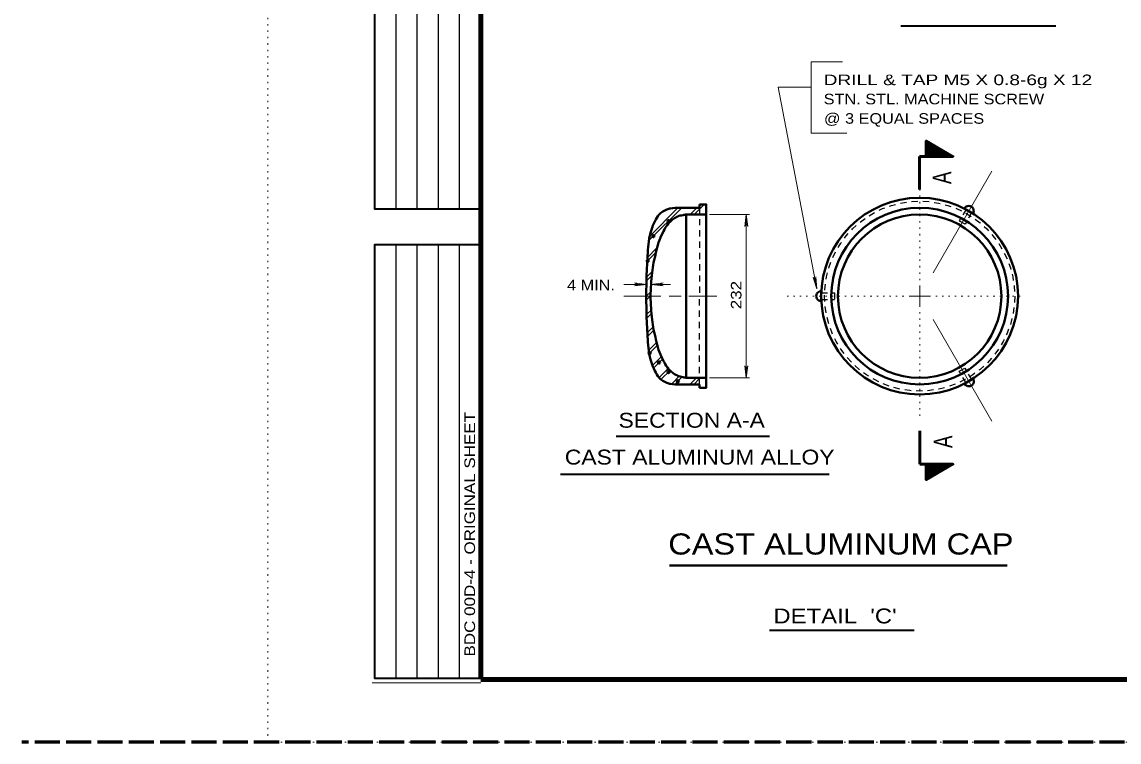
# Model space of a CAD drawing. Extents: x 312583 to 312854, y 144419 to 144597.
# Drawn here: x 312583.5 to 312662.4, y 144418.6 to 144470.4 of the extents above; entities that cross this region are included whole.
import ezdxf
from ezdxf.enums import TextEntityAlignment as Align

# ---------------------------------------------------------------- set-up
doc = ezdxf.new("R2010")
doc.units = 0
doc.header["$LTSCALE"] = 0.3
doc.header["$PDMODE"] = 32
doc.header["$PDSIZE"] = 0.15
for name, pattern in [('DOTTED', [1.5, 0.3, -1.2]), ('LONG_DASHED', [7.5, 6, -1.5]), ('SHORT_DASHED', [2.7, 1.5, -1.2])]:
    doc.linetypes.add(name, pattern=pattern)
for name, color, linetype, lineweight in [('1', 7, 'Continuous', 40), ('2', 7, 'Continuous', 13), ('62', 7, 'DOTTED', 13), ('63', 7, 'LONG_DASHED', 60)]:
    doc.layers.add(name, color=color, linetype=linetype, lineweight=lineweight)

msp = doc.modelspace()

# ---------------------------------------------------------------- linework, layer by layer
at = {"layer": '1', "lineweight": 25}
for p, q in [((312610.4087, 144456.901), (312610.4087, 144488.1192)), ((312611.9315, 144456.901), (312611.9315, 144488.1192)), ((312613.4543, 144456.901), (312613.4543, 144488.1192)), ((312614.9772, 144456.901), (312614.9772, 144488.1192)), ((312610.4087, 144423.1446), (312610.4087, 144454.3629)), ((312611.9315, 144423.1446), (312611.9315, 144454.3629)), ((312613.4543, 144423.1446), (312613.4543, 144454.3629)), ((312614.9772, 144423.1446), (312614.9772, 144454.3629))]:
    msp.add_line(p, q, dxfattribs=at)
at = {"layer": '1', "lineweight": 13}
for p, q in [((312653.2173, 144459.6302), (312649.0006, 144452.3239)), ((312628.6303, 144454.6852), (312630.9456, 144457.0006)), ((312628.6686, 144454.9919), (312630.6313, 144456.9622)), ((312631.5436, 144456.5176), (312632.0266, 144457.0006)), ((312631.8196, 144456.5176), (312632.5403, 144457.2382)), ((312632.2183, 144457.1922), (312632.2643, 144457.2382)), ((312628.4539, 144453.1596), (312629.0826, 144453.7806)), ((312628.4693, 144453.4356), (312629.1516, 144454.1256)), ((312628.4233, 144452.0402), (312628.8066, 144452.4236)), ((312628.4233, 144451.7642), (312628.7683, 144452.1092)), ((312628.3849, 144450.6526), (312628.7069, 144450.9669)), ((312628.3926, 144450.3842), (312628.6916, 144450.6756)), ((312628.4156, 144449.3186), (312628.7529, 144449.6559)), ((312628.4156, 144449.0502), (312628.7683, 144449.4029)), ((312653.2173, 144441.6596), (312649.0006, 144448.9659)), ((312628.4386, 144447.9846), (312628.9139, 144448.4599)), ((312628.4539, 144447.7316), (312628.9446, 144448.2299)), ((312628.5613, 144446.7579), (312629.0979, 144447.2946)), ((312628.5919, 144446.5126), (312629.1669, 144447.0952)), ((312628.8756, 144445.7152), (312629.4736, 144446.3132)), ((312628.9676, 144445.5389), (312629.5503, 144446.1139)), ((312629.3279, 144444.8106), (312629.9796, 144445.4622)), ((312629.4429, 144444.6572), (312630.1253, 144445.3319)), ((312630.2173, 144444.3506), (312630.7846, 144444.9179)), ((312630.4779, 144444.3352), (312630.9993, 144444.8566)), ((312631.5359, 144444.3122), (312632.0036, 144444.7799)), ((312631.8043, 144444.3046), (312632.2719, 144444.7799)), ((312632.6399, 144444.0592), (312632.7013, 144444.1129)), ((312608.6858, 144422.8446), (312616.5, 144422.8446))]:
    msp.add_line(p, q, dxfattribs=at)
at = {"layer": '1'}
for p, q in [((312632.2183, 144457.0006), (312630.7846, 144457.0006)), ((312632.2183, 144457.0006), (312632.2183, 144457.2382)), ((312651.2546, 144456.9469), (312651.8756, 144456.5942)), ((312631.2599, 144456.5176), (312631.2599, 144450.6449)), ((312632.7013, 144456.5176), (312632.7013, 144450.6449)), ((312631.2599, 144444.7799), (312631.2599, 144450.6449)), ((312632.7013, 144444.7799), (312632.7013, 144450.6449)), ((312640.9659, 144450.2922), (312640.9659, 144451.0052)), ((312632.2183, 144444.2969), (312630.7846, 144444.2969)), ((312632.2183, 144444.2969), (312632.2183, 144444.0592)), ((312651.8756, 144444.7032), (312651.2546, 144444.3506))]:
    msp.add_line(p, q, dxfattribs=at)
at = {"layer": '1', "linetype": 'SHORT_DASHED', "lineweight": 25}
for p, q in [((312632.2183, 144457.0006), (312632.2183, 144450.6449)), ((312651.3619, 144456.8856), (312650.8789, 144456.0576)), ((312651.2929, 144455.8199), (312650.8789, 144456.0576)), ((312651.7683, 144456.6479), (312651.2929, 144455.8199)), ((312632.2183, 144444.2969), (312632.2183, 144450.6449)), ((312640.9659, 144450.8826), (312641.9243, 144450.8826)), ((312641.9243, 144450.8826), (312641.9243, 144450.4072)), ((312640.9659, 144450.4072), (312641.9243, 144450.4072)), ((312650.8789, 144445.2399), (312651.2929, 144445.4776)), ((312651.3619, 144444.4042), (312650.8789, 144445.2399)), ((312651.7759, 144444.6496), (312651.2929, 144445.4776))]:
    msp.add_line(p, q, dxfattribs=at)
at = {"layer": '1', "lineweight": 158}
msp.add_line((312616.5, 144423.0846), (312849, 144423.0846), dxfattribs=at)
msp.add_lwpolyline([(312616.5, 144423.1446), (312616.5, 144585.0846), (312849, 144585.0846)], dxfattribs=at)
at = {"layer": '1', "lineweight": 35}
for points in [[(312616.5, 144456.901), (312608.8858, 144456.901), (312608.8858, 144488.1192), (312616.5, 144488.1192)], [(312616.5, 144423.1446), (312608.8858, 144423.1446), (312608.8858, 144454.3629), (312616.5, 144454.3629)]]:
    msp.add_lwpolyline(points, dxfattribs=at)
at = {"layer": '1'}
for points in [[(312631.2599, 144456.5176), (312632.7013, 144456.5176), (312632.7013, 144457.2382), (312632.2183, 144457.2382)], [(312631.2599, 144444.7799), (312632.7013, 144444.7799), (312632.7013, 144444.0592), (312632.2183, 144444.0592)]]:
    msp.add_lwpolyline(points, dxfattribs=at)
for radius in [7.0687, 6.3499, 5.8708]:
    msp.add_circle((312648.0308, 144450.6468), radius, dxfattribs=at)
at = {"layer": '1', "linetype": 'SHORT_DASHED', "lineweight": 25}
msp.add_circle((312648.0308, 144450.6468), 6.8291, dxfattribs=at)
at = {"layer": '1'}
for centre, start, end in [((312651.5658, 144456.7715), 329.52448, 150.47552), ((312640.9591, 144450.6459), 89.52448, 270.47552), ((312651.5674, 144444.5231), 209.52448, 30.47552)]:
    msp.add_arc(centre, 0.3575, start, end, dxfattribs=at)
for points in [[(312628.3849, 144450.6449), (312628.4079, 144452.0096), (312628.4923, 144453.7652), (312628.5689, 144454.5779), (312628.7529, 144455.4136), (312628.9983, 144456.0116), (312629.3126, 144456.5099), (312629.8723, 144456.8779), (312630.1329, 144456.9546), (312630.7846, 144457.0006)], [(312631.2599, 144456.5176), (312631.0299, 144456.4716), (312630.8153, 144456.4332), (312630.5009, 144456.3029), (312630.2019, 144456.0959), (312629.8186, 144455.6589), (312629.5733, 144455.1989), (312629.2743, 144454.5012), (312629.0826, 144453.7729), (312628.9139, 144453.0599), (312628.8066, 144452.3392), (312628.6839, 144450.6296)], [(312628.3849, 144450.6449), (312628.4079, 144449.2879), (312628.4923, 144447.5322), (312628.5689, 144446.7119), (312628.7529, 144445.8839), (312628.9983, 144445.2859), (312629.3126, 144444.7799), (312629.8723, 144444.4119), (312630.1329, 144444.3352), (312630.7846, 144444.2969)], [(312631.2599, 144444.7799), (312631.0299, 144444.8182), (312630.8153, 144444.8642), (312630.5009, 144444.9946), (312630.2019, 144445.2016), (312629.8186, 144445.6386), (312629.5733, 144446.0986), (312629.2743, 144446.7962), (312629.0826, 144447.5246), (312628.9139, 144448.2376), (312628.8066, 144448.9506), (312628.6839, 144450.6296)]]:
    msp.add_spline(points, degree=3, dxfattribs=at)
for p in [(312629.9873, 144456.0422), (312628.8986, 144454.9536), (312628.4923, 144453.1902), (312628.6303, 144446.5509), (312629.3049, 144445.8762), (312629.9873, 144445.1939), (312630.6619, 144444.5192)]:
    msp.add_point(p, dxfattribs=at)
at = {"layer": '2', "lineweight": 35}
for p, q in [((312646.6866, 144470.0876), (312657.8216, 144470.0876)), ((312648.5023, 144461.7769), (312648.5176, 144461.7922)), ((312648.5023, 144461.7309), (312648.5406, 144461.7846)), ((312648.5023, 144461.6772), (312648.5559, 144461.7692)), ((312648.5023, 144461.6312), (312648.5789, 144461.7539)), ((312648.5023, 144461.5776), (312648.6019, 144461.7462)), ((312648.5023, 144461.5392), (312648.6173, 144461.7309)), ((312648.5023, 144461.4856), (312648.6403, 144461.7232)), ((312648.5023, 144461.4396), (312648.6633, 144461.7079)), ((312648.5023, 144461.3936), (312648.6786, 144461.7002)), ((312648.5023, 144461.3476), (312648.7093, 144461.6849)), ((312648.5023, 144461.2939), (312648.7246, 144461.6772)), ((312648.5023, 144461.2479), (312648.7476, 144461.6619)), ((312648.5023, 144461.2019), (312648.7706, 144461.6542)), ((312648.5023, 144461.1482), (312648.7859, 144461.6389)), ((312648.5023, 144461.1022), (312648.8089, 144461.6312)), ((312648.5023, 144461.0562), (312648.8243, 144461.6159)), ((312648.5023, 144461.0026), (312648.8473, 144461.6006)), ((312648.5023, 144460.9566), (312648.8703, 144461.5929)), ((312648.5023, 144460.9106), (312648.8856, 144461.5776)), ((312648.5023, 144460.8646), (312648.9086, 144461.5622)), ((312648.5023, 144460.8109), (312648.9316, 144461.5546)), ((312648.5023, 144460.7726), (312648.9469, 144461.5392)), ((312648.5023, 144460.7189), (312648.9776, 144461.5316)), ((312648.5176, 144460.6959), (312648.9929, 144461.5162)), ((312648.5483, 144460.6959), (312649.0159, 144461.5086)), ((312648.5789, 144460.6959), (312649.0389, 144461.4932)), ((312648.6019, 144460.6959), (312649.0543, 144461.4856)), ((312648.6326, 144460.6959), (312649.0773, 144461.4702)), ((312648.6556, 144460.7036), (312649.1003, 144461.4626)), ((312648.6863, 144460.7036), (312649.1156, 144461.4472)), ((312648.7093, 144460.6959), (312649.1386, 144461.4396)), ((312648.7399, 144460.6959), (312649.1616, 144461.4242)), ((312648.7706, 144460.6959), (312649.1769, 144461.4089)), ((312648.7936, 144460.6959), (312649.1999, 144461.4012)), ((312648.8243, 144460.6959), (312649.2229, 144461.3859)), ((312648.8549, 144460.6959), (312649.2459, 144461.3706)), ((312648.8779, 144460.6959), (312649.2613, 144461.3629)), ((312648.9086, 144460.7036), (312649.2843, 144461.3476)), ((312648.9393, 144460.6959), (312649.3073, 144461.3399)), ((312648.9623, 144460.6959), (312649.3226, 144461.3246)), ((312648.9853, 144460.6959), (312649.3456, 144461.3169)), ((312649.0159, 144460.6959), (312649.3686, 144461.3016)), ((312649.0466, 144460.6959), (312649.3839, 144461.2939)), ((312649.0773, 144460.6959), (312649.4069, 144461.2786)), ((312649.1003, 144460.6959), (312649.4299, 144461.2709)), ((312649.1309, 144460.6959), (312649.4453, 144461.2556)), ((312649.1539, 144460.7036), (312649.4759, 144461.2479)), ((312649.1846, 144460.6959), (312649.4913, 144461.2326)), ((312649.2076, 144460.6959), (312649.5143, 144461.2172)), ((312649.2383, 144460.6959), (312649.5373, 144461.2096)), ((312649.2689, 144460.6959), (312649.5526, 144461.1942)), ((312649.2919, 144460.6959), (312649.5756, 144461.1866)), ((312649.3226, 144460.6959), (312649.5986, 144461.1712)), ((312649.3533, 144460.6959), (312649.6139, 144461.1636)), ((312649.3763, 144460.6959), (312649.6369, 144461.1482)), ((312649.4069, 144460.6959), (312649.6599, 144461.1406)), ((312649.4376, 144460.6959), (312649.6753, 144461.1252)), ((312649.4606, 144460.6959), (312649.6983, 144461.1176)), ((312649.4836, 144460.6959), (312649.7213, 144461.1022)), ((312649.5143, 144460.6959), (312649.7443, 144461.0946)), ((312649.5449, 144460.6959), (312649.7596, 144461.0792)), ((312649.5756, 144460.6959), (312649.7826, 144461.0639)), ((312649.5986, 144460.6959), (312649.8056, 144461.0562)), ((312649.6293, 144460.6959), (312649.8209, 144461.0409)), ((312649.6523, 144460.6959), (312649.8439, 144461.0256)), ((312649.6829, 144460.6959), (312649.8669, 144461.0179)), ((312649.7059, 144460.6959), (312649.8823, 144461.0026)), ((312649.7366, 144460.6959), (312649.9053, 144460.9949)), ((312649.7673, 144460.6959), (312649.9283, 144460.9796)), ((312649.7903, 144460.6959), (312649.9436, 144460.9719)), ((312649.8209, 144460.6959), (312649.9743, 144460.9566)), ((312649.8439, 144460.6959), (312649.9896, 144460.9489)), ((312649.8746, 144460.6959), (312650.0126, 144460.9336)), ((312649.9053, 144460.6959), (312650.0356, 144460.9259)), ((312649.9283, 144460.6959), (312650.0509, 144460.9106)), ((312649.9589, 144460.6959), (312650.0739, 144460.9029)), ((312649.9819, 144460.6959), (312650.0969, 144460.8876)), ((312650.0126, 144460.6959), (312650.1123, 144460.8722)), ((312650.0433, 144460.6959), (312650.1353, 144460.8646)), ((312650.0739, 144460.6959), (312650.1583, 144460.8492)), ((312650.0969, 144460.6959), (312650.1736, 144460.8339)), ((312650.1276, 144460.6959), (312650.1966, 144460.8262)), ((312650.1506, 144460.6959), (312650.2196, 144460.8109)), ((312650.1736, 144460.6959), (312650.2426, 144460.8032)), ((312650.2043, 144460.6959), (312650.2579, 144460.7879)), ((312650.2349, 144460.6959), (312650.2809, 144460.7802)), ((312650.2656, 144460.6959), (312650.3039, 144460.7649)), ((312650.2886, 144460.6959), (312650.3193, 144460.7572)), ((312650.3193, 144460.6959), (312650.3423, 144460.7419)), ((312650.3423, 144460.6959), (312650.3653, 144460.7342)), ((312650.3729, 144460.6959), (312650.3806, 144460.7189)), ((312650.4036, 144460.6959), (312650.4036, 144460.7112)), ((312626.2306, 144440.5786), (312637.2323, 144440.5786)), ((312622.2255, 144437.8492), (312641.5409, 144437.8492)), ((312648.5099, 144438.5392), (312648.9853, 144437.7266)), ((312648.5099, 144438.4856), (312648.9546, 144437.7189)), ((312648.5099, 144438.4472), (312648.9393, 144437.7036)), ((312648.5099, 144438.3936), (312648.9163, 144437.6959)), ((312648.5099, 144438.3476), (312648.8933, 144437.6806)), ((312648.5099, 144438.3016), (312648.8779, 144437.6652)), ((312648.5099, 144438.2556), (312648.8549, 144437.6576)), ((312648.5099, 144438.2019), (312648.8319, 144437.6422)), ((312648.5099, 144438.1559), (312648.8166, 144437.6269)), ((312648.5099, 144438.1099), (312648.7936, 144437.6192)), ((312648.5099, 144438.0562), (312648.7783, 144437.6039)), ((312648.5099, 144438.0102), (312648.7553, 144437.5962)), ((312648.5099, 144437.9642), (312648.7323, 144437.5809)), ((312648.5099, 144437.9106), (312648.7169, 144437.5732)), ((312648.5099, 144437.8646), (312648.6863, 144437.5579)), ((312648.5253, 144438.5622), (312649.0006, 144437.7419)), ((312648.5559, 144438.5622), (312649.0236, 144437.7496)), ((312648.5866, 144438.5622), (312649.0466, 144437.7649)), ((312648.6096, 144438.5622), (312649.0619, 144437.7726)), ((312648.6403, 144438.5622), (312649.0849, 144437.7879)), ((312648.6633, 144438.5546), (312649.1079, 144437.7956)), ((312648.6939, 144438.5546), (312649.1233, 144437.8109)), ((312648.7169, 144438.5622), (312649.1463, 144437.8186)), ((312648.7476, 144438.5622), (312649.1693, 144437.8339)), ((312648.7783, 144438.5622), (312649.1846, 144437.8492)), ((312648.8013, 144438.5622), (312649.2076, 144437.8569)), ((312648.8319, 144438.5622), (312649.2306, 144437.8722)), ((312648.8626, 144438.5622), (312649.2536, 144437.8876)), ((312648.8856, 144438.5622), (312649.2689, 144437.8952)), ((312648.9163, 144438.5546), (312649.2919, 144437.9106)), ((312648.9469, 144438.5622), (312649.3149, 144437.9182)), ((312648.9699, 144438.5622), (312649.3303, 144437.9336)), ((312648.9929, 144438.5622), (312649.3533, 144437.9412)), ((312649.0236, 144438.5622), (312649.3763, 144437.9566)), ((312649.0543, 144438.5622), (312649.3916, 144437.9642)), ((312649.0849, 144438.5622), (312649.4146, 144437.9796)), ((312649.1079, 144438.5622), (312649.4376, 144437.9872)), ((312649.1386, 144438.5622), (312649.4529, 144438.0026)), ((312649.1616, 144438.5546), (312649.4836, 144438.0102)), ((312649.1923, 144438.5622), (312649.4989, 144438.0256)), ((312649.2153, 144438.5622), (312649.5219, 144438.0409)), ((312649.2459, 144438.5622), (312649.5449, 144438.0486)), ((312649.2766, 144438.5622), (312649.5603, 144438.0639)), ((312649.2996, 144438.5622), (312649.5833, 144438.0716)), ((312649.3303, 144438.5622), (312649.6063, 144438.0869)), ((312649.3609, 144438.5622), (312649.6216, 144438.0946)), ((312649.3839, 144438.5622), (312649.6446, 144438.1099)), ((312649.4146, 144438.5622), (312649.6676, 144438.1176)), ((312649.4453, 144438.5622), (312649.6829, 144438.1329)), ((312649.4683, 144438.5622), (312649.7059, 144438.1406)), ((312649.4913, 144438.5622), (312649.7289, 144438.1559)), ((312649.5219, 144438.5622), (312649.7519, 144438.1636)), ((312649.5526, 144438.5622), (312649.7673, 144438.1789)), ((312649.5833, 144438.5622), (312649.7903, 144438.1942)), ((312649.6063, 144438.5622), (312649.8133, 144438.2019)), ((312649.6369, 144438.5622), (312649.8286, 144438.2172)), ((312649.6599, 144438.5622), (312649.8516, 144438.2326)), ((312649.6906, 144438.5622), (312649.8746, 144438.2402)), ((312649.7136, 144438.5622), (312649.8899, 144438.2556)), ((312649.7443, 144438.5622), (312649.9129, 144438.2632)), ((312649.7749, 144438.5622), (312649.9359, 144438.2786)), ((312649.7979, 144438.5622), (312649.9513, 144438.2862)), ((312649.8286, 144438.5622), (312649.9819, 144438.3016)), ((312649.8516, 144438.5622), (312649.9973, 144438.3092)), ((312649.8823, 144438.5622), (312650.0203, 144438.3246)), ((312649.9129, 144438.5622), (312650.0433, 144438.3322)), ((312649.9359, 144438.5622), (312650.0586, 144438.3476)), ((312649.9666, 144438.5622), (312650.0816, 144438.3552)), ((312649.9896, 144438.5622), (312650.1046, 144438.3706)), ((312650.0203, 144438.5622), (312650.1199, 144438.3859)), ((312650.0509, 144438.5622), (312650.1429, 144438.3936)), ((312650.0816, 144438.5622), (312650.1659, 144438.4089)), ((312650.1046, 144438.5622), (312650.1813, 144438.4242)), ((312650.1353, 144438.5622), (312650.2043, 144438.4319)), ((312650.1583, 144438.5622), (312650.2273, 144438.4472)), ((312650.1813, 144438.5622), (312650.2503, 144438.4549)), ((312650.2119, 144438.5622), (312650.2656, 144438.4702)), ((312650.2426, 144438.5622), (312650.2886, 144438.4779)), ((312650.2733, 144438.5622), (312650.3116, 144438.4932)), ((312650.2963, 144438.5622), (312650.3269, 144438.5009)), ((312650.3269, 144438.5622), (312650.3499, 144438.5162)), ((312650.3499, 144438.5622), (312650.3729, 144438.5239)), ((312650.3806, 144438.5622), (312650.3883, 144438.5392)), ((312650.4113, 144438.5622), (312650.4113, 144438.5469)), ((312648.5099, 144437.8186), (312648.6709, 144437.5502)), ((312648.5099, 144437.7726), (312648.6479, 144437.5349)), ((312648.5099, 144437.7189), (312648.6249, 144437.5272)), ((312648.5099, 144437.6806), (312648.6096, 144437.5119)), ((312648.5099, 144437.6269), (312648.5866, 144437.5042)), ((312648.5099, 144437.5809), (312648.5636, 144437.4889)), ((312648.5099, 144437.5272), (312648.5483, 144437.4736)), ((312648.5099, 144437.4812), (312648.5253, 144437.4659)), ((312637.2323, 144426.6216), (312647.6489, 144426.6216))]:
    msp.add_line(p, q, dxfattribs=at)
at = {"layer": '2'}
for p, q in [((312640.2299, 144465.6792), (312637.8609, 144465.6792)), ((312640.6439, 144451.1662), (312637.8609, 144465.6792)), ((312640.2299, 144462.3519), (312642.8059, 144462.3519)), ((312632.9389, 144456.5176), (312635.8139, 144456.5176)), ((312635.5763, 144456.5176), (312635.4689, 144455.6512)), ((312635.5763, 144444.7799), (312635.5763, 144456.5176)), ((312635.5763, 144456.5176), (312635.6836, 144455.6512)), ((312635.4689, 144455.6512), (312635.5763, 144455.9272)), ((312635.6836, 144455.6512), (312635.5763, 144455.9272)), ((312640.5826, 144452.0402), (312640.5289, 144451.7412)), ((312640.6439, 144451.1662), (312640.5826, 144452.0402)), ((312626.7826, 144451.4882), (312628.4003, 144451.4882)), ((312627.5339, 144451.5956), (312627.8099, 144451.4882)), ((312628.4003, 144451.4882), (312627.5339, 144451.5956)), ((312627.5339, 144451.3809), (312627.8099, 144451.4882)), ((312628.4003, 144451.4882), (312627.5339, 144451.3809)), ((312628.7453, 144451.4882), (312629.6116, 144451.5956)), ((312630.1253, 144451.4882), (312628.7453, 144451.4882)), ((312628.7453, 144451.4882), (312629.6116, 144451.3809)), ((312629.6116, 144451.5956), (312629.3356, 144451.4882)), ((312629.6116, 144451.3809), (312629.3356, 144451.4882)), ((312640.3756, 144451.9942), (312640.5289, 144451.7412)), ((312640.6439, 144451.1662), (312640.3756, 144451.9942)), ((312648.0346, 144450.6449), (312648.0346, 144451.4116)), ((312626.7826, 144450.6449), (312629.4353, 144450.6449)), ((312630.0333, 144450.6449), (312630.8843, 144450.6449)), ((312631.4363, 144450.6449), (312633.4603, 144450.6449)), ((312648.0346, 144450.6449), (312647.2679, 144450.6449)), ((312648.0346, 144450.6449), (312647.2679, 144450.6449)), ((312648.0346, 144450.6449), (312648.0346, 144449.8782)), ((312648.0346, 144450.6449), (312648.8013, 144450.6449)), ((312635.4689, 144445.6462), (312635.5763, 144445.3702)), ((312635.5763, 144444.7799), (312635.4689, 144445.6462)), ((312635.6836, 144445.6462), (312635.5763, 144445.3702)), ((312635.5763, 144444.7799), (312635.6836, 144445.6462)), ((312632.9389, 144444.7799), (312635.8139, 144444.7799))]:
    msp.add_line(p, q, dxfattribs=at)
at = {"layer": '2', "lineweight": 53}
for p, q in [((312648.0269, 144458.3039), (312648.0269, 144460.6959)), ((312648.5023, 144460.6959), (312648.0269, 144460.6959)), ((312648.0346, 144440.9542), (312648.0346, 144438.5622)), ((312648.5099, 144438.5622), (312648.0346, 144438.5622))]:
    msp.add_line(p, q, dxfattribs=at)
at = {"layer": '2', "linetype": 'DOTTED'}
for p, q in [((312648.0346, 144451.7949), (312648.0346, 144459.4616)), ((312646.8846, 144450.6449), (312638.1676, 144450.6449)), ((312649.1846, 144450.6449), (312655.4099, 144450.6449)), ((312648.0346, 144449.4949), (312648.0346, 144441.9509))]:
    msp.add_line(p, q, dxfattribs=at)
at = {"layer": '2', "lineweight": 40}
msp.add_line((312630.0488, 144431.289), (312654.3302, 144431.289), dxfattribs=at)
at = {"layer": '2'}
msp.add_lwpolyline([(312640.2299, 144462.3519), (312640.2299, 144467.4962), (312642.4763, 144467.4962)], dxfattribs=at)
at = {"layer": '2', "lineweight": 53}
for points in [[(312648.5023, 144460.6959), (312648.5023, 144461.8076), (312650.4189, 144460.6959)], [(312648.5099, 144438.5622), (312648.5099, 144437.4506), (312650.4266, 144438.5622)]]:
    msp.add_lwpolyline(points, close=True, dxfattribs=at)
at = {"layer": '62'}
msp.add_line((312601.2, 144418.5846), (312601.2, 144596.7846), dxfattribs=at)
msp.add_lwpolyline([(312601.2, 144418.5846), (312853.5, 144418.5846), (312853.5, 144596.7846)], dxfattribs=at)
at = {"layer": '63'}
msp.add_line((312851.75, 144418.5846), (312583.526, 144418.5846), dxfattribs=at)

# ---------------------------------------------------------------- texts
at = {"layer": '1', "width": 1.2}
msp.add_text('BDC 00D-4 - ORIGINAL SHEET', height=0.7614, rotation=90, dxfattribs=at).set_placement((312616.0832, 144424.7374))
at = {"layer": '2'}
for s, height, width, p in [('DRILL & TAP M5 X 0.8-6g X 12', 0.76, 1.35, (312641.1346, 144465.8162)), ('STN. STL. MACHINE SCREW', 0.76, 1.15, (312641.1346, 144464.4362)), ('@ 3 EQUAL SPACES', 0.76, 1.15, (312641.1576, 144463.0409)), ('4 MIN.', 0.76, 1.15, (312622.6965, 144451.0591)), ('SECTION A-A', 1.07, 1.15, (312626.395, 144441.1861)), ('CAST ALUMINUM ALLOY', 1.07, 1.15, (312622.5336, 144438.5383)), ('CAST ALUMINUM CAP', 1.52, 1.15, (312629.9681, 144432.0667)), ("DETAIL  'C'", 1.07, 1.2, (312637.5187, 144427.1165))]:
    msp.add_text(s, height=height, dxfattribs=dict(at, width=width)).set_placement(p)
at = {"layer": '2', "width": 0.75}
for p in [(312650.2963, 144459.1549), (312650.3806, 144440.1722)]:
    msp.add_text('A', height=1.34, rotation=90, dxfattribs=at).set_placement(p, align=Align.CENTER)
at = {"layer": '2', "width": 1.2}
msp.add_text('232 ', height=0.76, rotation=90, dxfattribs=at).set_placement((312635.2273, 144449.7054))

doc.saveas('drawing.dxf')
